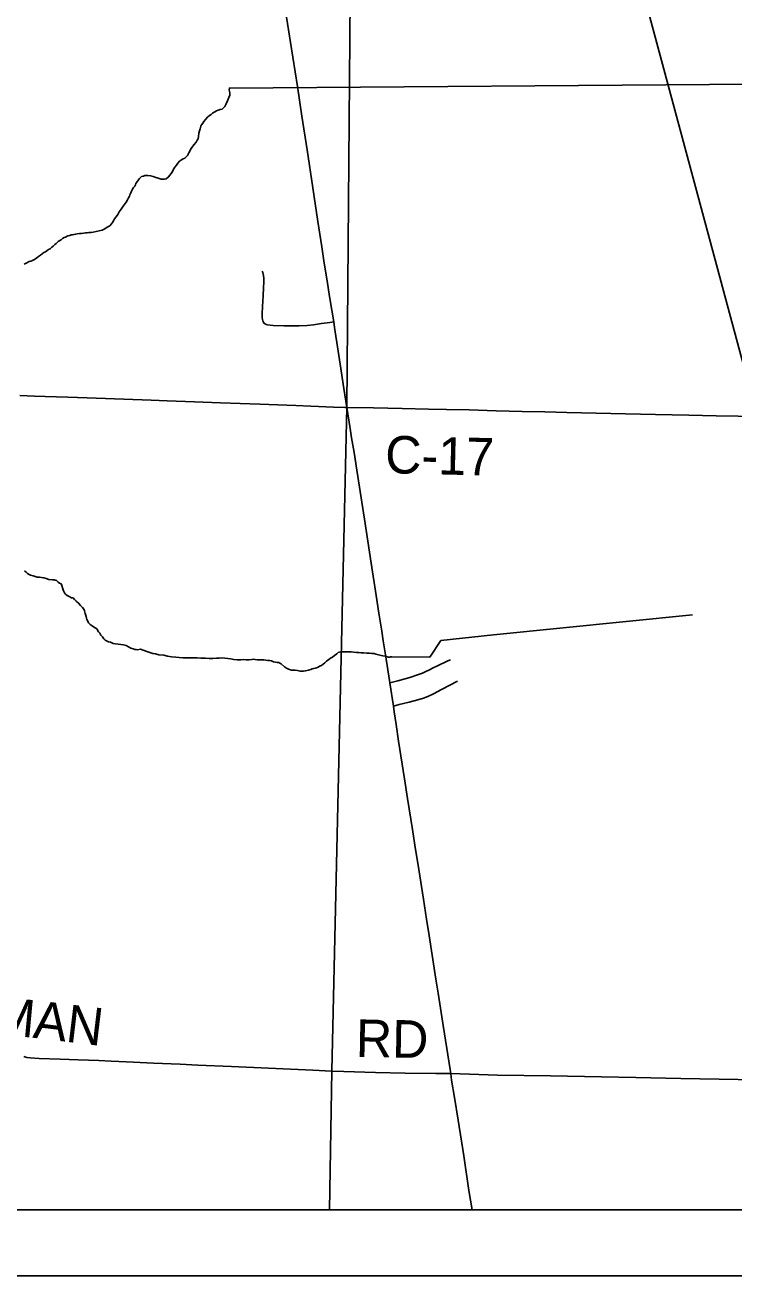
# Model space of a CAD drawing. Extents: x 0 to 34, y 0 to 22.
# Drawn here: x 28.306 to 29.379, y 14 to 15.894 of the extents above; entities that cross this region are included whole.
import ezdxf

# ---------------------------------------------------------------- set-up
doc = ezdxf.new("R2010")
doc.units = 0
for name, color, linetype in [('GM_X_County_Road', 7, 'Continuous'), ('GM_X_County_Road_Text', 7, 'Continuous'), ('GM_X_Minor_River', 7, 'Continuous'), ('GM_X_Rail_Line', 7, 'Continuous'), ('GM_X_State_Route', 7, 'Continuous'), ('GM_X_Township_Road', 7, 'Continuous'), ('GM_X_Township_Road_Text', 7, 'Continuous'), ('SH_Data', 7, 'Continuous')]:
    doc.layers.add(name, color=color, linetype=linetype)

msp = doc.modelspace()

# ---------------------------------------------------------------- linework, layer by layer
at = {"layer": 'GM_X_County_Road'}
for points in [[(28.2983, 15.3332), (28.3206, 15.3323), (28.3369, 15.3317), (28.3709, 15.3305), (28.4001, 15.3295), (28.4971, 15.3259), (28.5213, 15.325), (28.5629, 15.3236), (28.602, 15.322), (28.6617, 15.3201), (28.7163, 15.3179), (28.7387, 15.3169), (28.773, 15.3157), (28.7905, 15.3151), (28.7936, 15.315)], [(28.7936, 15.315), (28.8337, 15.3144), (28.8772, 15.3137), (28.917, 15.3126), (28.9444, 15.312), (28.9785, 15.3113), (29.0196, 15.3102), (29.0587, 15.3091), (29.0929, 15.3084), (29.1265, 15.3075), (29.2153, 15.3055), (29.2607, 15.3045), (29.3111, 15.3034), (29.3527, 15.3023), (29.3857, 15.3017), (29.4167, 15.301), (29.4702, 15.3003), (29.4895, 15.2997), (29.5858, 15.298), (29.6169, 15.2971), (29.6766, 15.2959), (29.7101, 15.295), (29.7239, 15.2949)]]:
    msp.add_lwpolyline(points, dxfattribs=at)
at = {"layer": 'GM_X_Minor_River'}
for points in [[(28.4403, 15.5978), (28.4419, 15.6005), (28.4442, 15.6038), (28.4466, 15.6072), (28.4489, 15.6113), (28.4517, 15.6155), (28.4548, 15.62), (28.4592, 15.626), (28.4615, 15.6297), (28.4631, 15.6324), (28.4643, 15.635), (28.4651, 15.6373), (28.4663, 15.6399), (28.4675, 15.6425), (28.4687, 15.6456), (28.4707, 15.6482), (28.4723, 15.6504), (28.4734, 15.6523), (28.4742, 15.6542), (28.4754, 15.6564), (28.4778, 15.6598), (28.4793, 15.6617), (28.4828, 15.6647), (28.4855, 15.6654), (28.4878, 15.6661), (28.4901, 15.6664), (28.4924, 15.6663), (28.4962, 15.6659), (28.4981, 15.6655), (28.5, 15.6647), (28.5019, 15.6642), (28.5041, 15.6634), (28.5064, 15.663), (28.5091, 15.6618), (28.5121, 15.661), (28.5151, 15.6609), (28.5174, 15.6608), (28.5197, 15.6612), (28.5236, 15.6641), (28.5291, 15.6716), (28.5307, 15.675), (28.533, 15.6788), (28.5354, 15.6818), (28.5377, 15.6848), (28.5401, 15.6881), (28.5432, 15.69), (28.5455, 15.6914), (28.5482, 15.6925), (28.5521, 15.6966), (28.5544, 15.7008), (28.558, 15.7071), (28.5619, 15.7128), (28.5651, 15.7169), (28.567, 15.7199), (28.5682, 15.7221), (28.569, 15.7252), (28.5695, 15.7305), (28.5704, 15.7339), (28.5712, 15.7369), (28.5724, 15.7411), (28.5736, 15.7433), (28.5752, 15.7456), (28.5768, 15.7482), (28.5795, 15.7512), (28.5826, 15.7546), (28.5857, 15.7572), (28.588, 15.7586), (28.59, 15.7605), (28.5935, 15.7627), (28.5962, 15.7642), (28.5988, 15.7653), (28.6019, 15.7663), (28.6046, 15.767), (28.6069, 15.7689), (28.6085, 15.7707), (28.6105, 15.7749), (28.6129, 15.7794), (28.6149, 15.7843), (28.6161, 15.7881), (28.6161, 15.7908), (28.6158, 15.7942), (28.6155, 15.7961), (28.6156, 15.7988), (28.6155, 15.7984)], [(28.6156, 15.7988), (29.4085, 15.8047)], [(28.3048, 15.5319), (28.3091, 15.5341), (28.3125, 15.5359), (28.3152, 15.5366), (28.3175, 15.5377), (28.3198, 15.5388), (28.3221, 15.5403), (28.3241, 15.5418), (28.3268, 15.5436), (28.3295, 15.5458), (28.3322, 15.5477), (28.3349, 15.5495), (28.3372, 15.551), (28.3395, 15.5525), (28.3419, 15.5543), (28.3442, 15.5554), (28.3469, 15.5576), (28.3488, 15.5591), (28.3516, 15.5621), (28.3535, 15.5632), (28.3566, 15.5662), (28.3589, 15.5677), (28.3608, 15.5691), (28.3628, 15.571), (28.3655, 15.5725), (28.3674, 15.5732), (28.3713, 15.575), (28.3739, 15.5757), (28.3762, 15.5764), (28.3781, 15.5764), (28.3804, 15.5771), (28.3827, 15.5774), (28.3854, 15.5781), (28.3885, 15.5784), (28.3919, 15.5787), (28.3946, 15.579), (28.3976, 15.5794), (28.4003, 15.5797), (28.403, 15.58), (28.406, 15.5799), (28.4095, 15.5806), (28.4228, 15.5838), (28.4271, 15.5856), (28.4306, 15.5882), (28.4344, 15.59), (28.4371, 15.593), (28.4387, 15.5952), (28.4403, 15.5978)], [(28.3052, 15.0675), (28.3082, 15.0655), (28.3101, 15.0639), (28.3123, 15.0624), (28.3146, 15.0612), (28.3184, 15.0603), (28.3218, 15.0591), (28.3248, 15.0583), (28.3278, 15.0582), (28.3313, 15.0574), (28.3347, 15.0569), (28.3385, 15.0561), (28.3422, 15.0545), (28.3479, 15.054), (28.3502, 15.0539), (28.3521, 15.0535), (28.354, 15.0531), (28.3566, 15.0507), (28.3585, 15.0491)], [(28.3585, 15.0491), (28.3608, 15.048), (28.3622, 15.0453), (28.3633, 15.0407), (28.3643, 15.0372), (28.3662, 15.0345), (28.3677, 15.0326), (28.3699, 15.0306), (28.3729, 15.0287), (28.3767, 15.027), (28.379, 15.0266), (28.3812, 15.0243), (28.3838, 15.0216), (28.3872, 15.0188), (28.3901, 15.0153), (28.3931, 15.0122), (28.3954, 15.0099), (28.3964, 15.0072), (28.3975, 15.003), (28.3986, 14.9988), (28.3993, 14.9961), (28.4, 14.9942), (28.4011, 14.9915), (28.4025, 14.9888), (28.4051, 14.9864), (28.4081, 14.9845), (28.41, 14.9829), (28.4126, 14.9813), (28.4149, 14.9798), (28.4175, 14.9755), (28.4193, 14.9732), (28.4212, 14.9705), (28.4234, 14.9678), (28.4256, 14.9647), (28.4275, 14.9627), (28.4298, 14.9619), (28.4328, 14.9603), (28.4354, 14.9595), (28.4377, 14.9587), (28.4396, 14.9575), (28.4434, 14.957), (28.4472, 14.9566), (28.4513, 14.9561), (28.4555, 14.9556), (28.4593, 14.9548), (28.4631, 14.9528), (28.4665, 14.9508), (28.4699, 14.9496), (28.4725, 14.9484), (28.4744, 14.9484), (28.4767, 14.9483), (28.4809, 14.949), (28.4907, 14.9457), (28.4952, 14.9441), (28.4998, 14.9428), (28.504, 14.942), (28.5089, 14.9407), (28.5165, 14.9398), (28.5218, 14.9385), (28.5282, 14.9376), (28.5347, 14.9371), (28.5396, 14.9366), (28.545, 14.9361), (28.5495, 14.936), (28.5533, 14.9359), (28.5575, 14.9359), (28.5621, 14.9361), (28.567, 14.936), (28.5724, 14.9355), (28.5796, 14.9354), (28.5849, 14.9352), (28.5906, 14.9351), (28.596, 14.9354), (28.6002, 14.9357), (28.6044, 14.936), (28.6089, 14.9355), (28.6131, 14.935), (28.6173, 14.9345), (28.6222, 14.9337), (28.6275, 14.9332), (28.6329, 14.933), (28.6367, 14.9333), (28.6412, 14.9332), (28.6458, 14.9331), (28.6496, 14.9334), (28.6519, 14.9338), (28.6546, 14.9333), (28.6576, 14.9332), (28.6607, 14.9332), (28.6641, 14.9331), (28.6679, 14.933), (28.6706, 14.9326), (28.674, 14.9321), (28.6766, 14.9317), (28.6793, 14.9312), (28.6823, 14.93), (28.6853, 14.9296), (28.688, 14.9291), (28.6903, 14.9287), (28.6922, 14.9279), (28.694, 14.9271)], [(28.8614, 14.9375), (28.9189, 14.937), (28.9358, 14.9621), (29.0152, 14.9706), (29.3167, 15.0012)], [(28.694, 14.9271), (28.6989, 14.9224), (28.7023, 14.9201), (28.7053, 14.9189), (28.7079, 14.918), (28.7098, 14.9172), (28.7125, 14.9172), (28.7152, 14.9171), (28.7186, 14.9167), (28.7227, 14.9158), (28.7277, 14.9157), (28.7308, 14.9164), (28.7353, 14.9171), (28.7388, 14.9185), (28.7411, 14.9192), (28.7434, 14.9199), (28.7457, 14.9203), (28.7476, 14.921), (28.7499, 14.9221), (28.7522, 14.9232), (28.7549, 14.9246), (28.7576, 14.9265), (28.7599, 14.9283), (28.7627, 14.9309), (28.7662, 14.9335), (28.7685, 14.9354), (28.7716, 14.9368), (28.7747, 14.9394), (28.7781, 14.942), (28.7801, 14.9439), (28.7843, 14.9449), (28.7881, 14.9452), (28.7915, 14.9451), (28.7942, 14.9451), (28.7965, 14.945), (28.7999, 14.9449), (28.8037, 14.9445), (28.8079, 14.944), (28.8117, 14.9439), (28.8151, 14.9435), (28.8185, 14.9434), (28.8235, 14.9433), (28.8277, 14.9432), (28.8315, 14.9423), (28.8349, 14.9423), (28.8375, 14.9414), (28.8455, 14.9397), (28.8481, 14.9389), (28.8512, 14.9385), (28.8535, 14.938), (28.8561, 14.9372), (28.8584, 14.9372), (28.8599, 14.9375), (28.8614, 14.9375)]]:
    msp.add_lwpolyline(points, dxfattribs=at)
at = {"layer": 'GM_X_Rail_Line'}
msp.add_lwpolyline([(29.7358, 14.1), (29.6819, 14.2915), (29.4151, 15.3006), (29.1953, 16.1186), (28.963, 16.952), (28.8642, 17.3725), (28.8153, 17.4999), (28.7556, 17.6382), (28.6863, 17.7778), (28.4883, 18.0894), (28.4584, 18.1342), (28.4272, 18.1626), (28.3947, 18.1748), (28.3594, 18.181)], dxfattribs=at)
at = {"layer": 'GM_X_State_Route'}
for points in [[(28.6977, 15.9355), (28.708, 15.8679), (28.7185, 15.8009), (28.7253, 15.7561), (28.7334, 15.7051), (28.742, 15.6479), (28.7497, 15.5969), (28.7558, 15.5582), (28.7578, 15.5441), (28.7593, 15.5336), (28.7631, 15.5097), (28.7678, 15.4802), (28.7735, 15.4448), (28.7749, 15.436), (28.7803, 15.4004), (28.7835, 15.3807), (28.7891, 15.3439), (28.7936, 15.315)], [(28.7936, 15.315), (28.7985, 15.283), (28.8007, 15.2689), (28.8043, 15.2468), (28.8083, 15.2204), (28.82, 15.1461), (28.8304, 15.0791), (28.8379, 15.0306), (28.8418, 15.0035), (28.8462, 14.9765), (28.8484, 14.9618), (28.8519, 14.9403), (28.8578, 14.9016), (28.8583, 14.8983), (28.8638, 14.8629), (28.8651, 14.8543), (28.8681, 14.8352), (28.8718, 14.81), (28.8808, 14.7529), (28.8854, 14.7228), (28.8927, 14.6761), (28.8965, 14.6522), (28.9024, 14.6153), (28.9094, 14.5705), (28.914, 14.5404), (28.9182, 14.5153), (28.9282, 14.4495), (28.9315, 14.428), (28.935, 14.4053), (28.9393, 14.3795), (28.9449, 14.3445), (28.9497, 14.3125), (28.9506, 14.3064), (28.952, 14.2965), (28.9563, 14.2702), (28.9617, 14.2358), (28.9703, 14.1817), (28.9783, 14.1295), (28.983, 14.1)]]:
    msp.add_lwpolyline(points, dxfattribs=at)
at = {"layer": 'GM_X_Township_Road'}
for points in [[(23.5167, 18.4074), (23.5167, 14.1), (28.7673, 14.1), (28.7709, 14.3107), (28.7934, 15.3155), (28.8021, 16.3696)], [(28.6679, 15.4429), (28.667, 15.4444), (28.6661, 15.4461), (28.6655, 15.4482), (28.6651, 15.4515), (28.6651, 15.4571), (28.6657, 15.4682), (28.6667, 15.4839), (28.6673, 15.4969), (28.6677, 15.5049), (28.6676, 15.5105), (28.6673, 15.5151), (28.6662, 15.5197), (28.6654, 15.5216)], [(28.6679, 15.4429), (28.6697, 15.4416), (28.6713, 15.4408), (28.6735, 15.4401), (28.6771, 15.4395), (28.6818, 15.439), (28.6978, 15.4389), (28.7108, 15.4387), (28.7214, 15.4388), (28.7332, 15.4393), (28.743, 15.4404), (28.7553, 15.442), (28.7676, 15.4439), (28.7735, 15.4448)], [(28.8583, 14.8983), (28.8706, 14.9013), (28.8889, 14.9061), (28.9006, 14.9101), (28.9081, 14.913), (28.9131, 14.9152), (28.9184, 14.918), (28.9233, 14.9203), (28.9315, 14.9242), (28.9441, 14.9304), (28.9464, 14.9315), (28.9503, 14.9332)], [(28.8638, 14.8629), (28.8727, 14.8653), (28.8878, 14.8688), (28.901, 14.8724), (28.9093, 14.8748), (28.9161, 14.8772), (28.9248, 14.8813), (28.9369, 14.8878), (28.9611, 14.9005)], [(28.3043, 14.3321), (28.3092, 14.3309), (28.314, 14.3303), (28.3277, 14.3295), (28.3592, 14.3284), (28.3867, 14.3274), (28.4181, 14.3263), (28.4367, 14.3253), (28.4485, 14.3247), (28.4703, 14.3237), (28.5007, 14.3223), (28.5411, 14.3205), (28.5678, 14.3193), (28.6187, 14.317), (28.7417, 14.3114), (28.7701, 14.3102)], [(28.7701, 14.3102), (28.7711, 14.3102), (28.7889, 14.3094), (28.8367, 14.3083), (28.8815, 14.3073), (28.9281, 14.3066), (28.9437, 14.3065), (28.9506, 14.3064)], [(28.9506, 14.3064), (29.0216, 14.3042), (29.1018, 14.3029), (29.1789, 14.3014), (29.2311, 14.3005), (29.2989, 14.299), (29.3859, 14.2976), (29.4617, 14.2961), (29.4897, 14.2955), (29.5139, 14.2949), (29.5674, 14.2942), (29.6438, 14.2924), (29.6967, 14.2912)]]:
    msp.add_lwpolyline(points, dxfattribs=at)
msp.add_lwpolyline([(28.7673, 14.1), (30.3167, 14.1), (30.3167, 16.335), (30.315, 16.335), (30.2735, 16.3357), (30.2681, 16.3359), (30.2361, 16.3375), (29.7483, 16.3505), (28.8021, 16.3696), (28.7934, 15.3155), (28.7709, 14.3107)], close=True, dxfattribs=at)
at = {"layer": 'SH_Data'}
for points in [[(23.4167, 21), (30.4167, 21), (30.4167, 14), (23.4167, 14)], [(23.5167, 20.9), (30.3167, 20.9), (30.3167, 14.1), (23.5167, 14.1)]]:
    msp.add_lwpolyline(points, close=True, dxfattribs=at)

# ---------------------------------------------------------------- texts
at = {"layer": 'GM_X_County_Road_Text'}
msp.add_text('C-17', height=0.05682, rotation=358.6283, dxfattribs=at).set_placement((28.8509, 15.2157))
at = {"layer": 'GM_X_Township_Road_Text'}
for s, height, rotation, p in [('M', 0.0568, 354.6922, (28.2559, 14.3665)), ('A', 0.0568, 353.1077, (28.3169, 14.3609)), ('N', 0.0568, 353.1211, (28.3666, 14.3549)), ('RD', 0.05682, 359.0223, (28.8067, 14.3318))]:
    msp.add_text(s, height=height, rotation=rotation, dxfattribs=at).set_placement(p)

doc.saveas('drawing.dxf')
